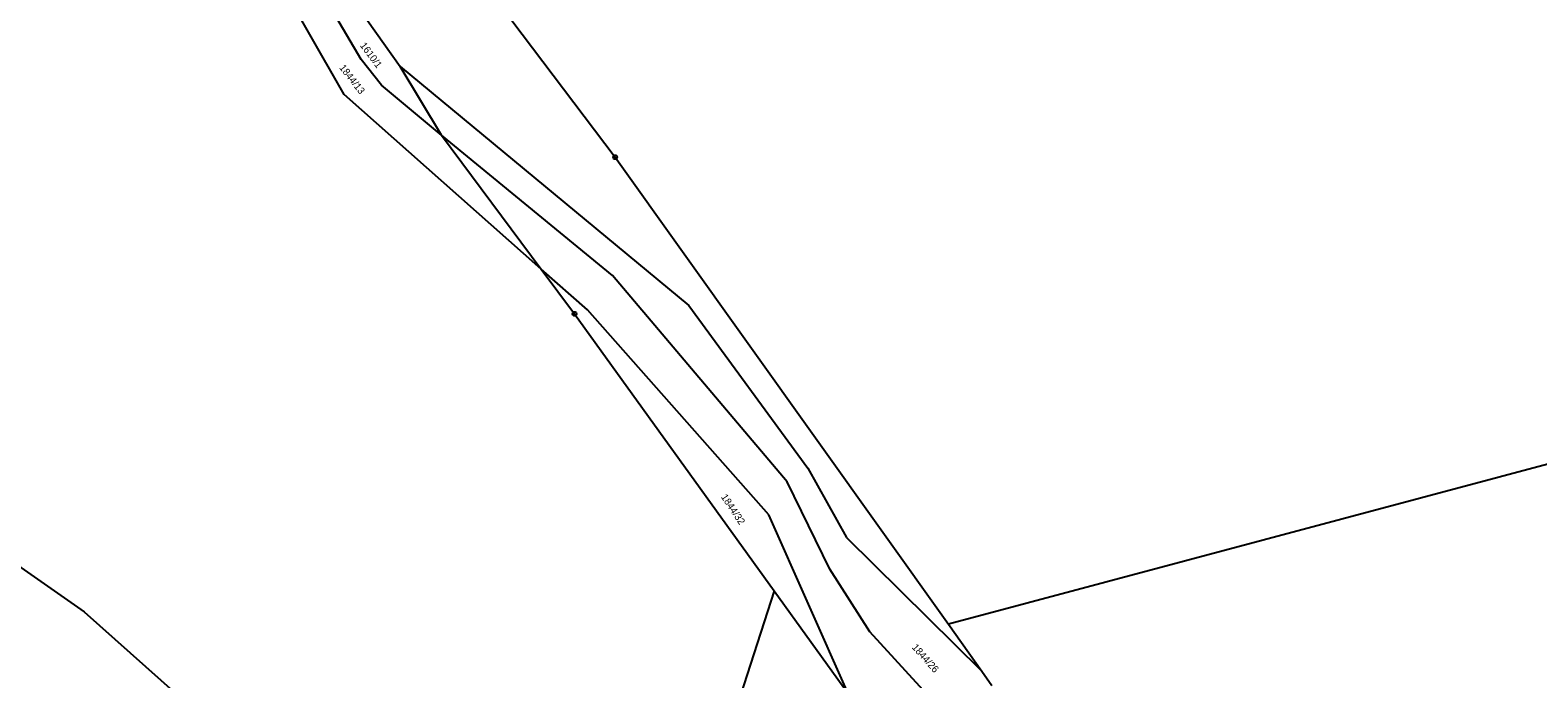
# Model space of a CAD drawing. Extents: x -747792 to -745414, y -1093712 to -1091463.
# Drawn here: x -747209.9 to -747029.6, y -1092023.4 to -1091945.8 of the extents above; entities that cross this region are included whole.
import ezdxf

# ---------------------------------------------------------------- set-up
doc = ezdxf.new("R2010")
doc.units = 0
for name, color, linetype in [('Pracovní_bod JDTM STC_VC', 7, 'Continuous'), ('Pracovní_bod NN - výška', 7, 'Continuous'), ('Pracovní_bod VN - výška', 7, 'Continuous')]:
    doc.layers.add(name, color=color, linetype=linetype)

msp = doc.modelspace()

# ---------------------------------------------------------------- linework, layer by layer
at = {"layer": 'Pracovní_bod NN - výška'}
for points in [[(-747172.39, -1091953.51), (-747197.99, -1091908.69)], [(-747167.26, -1091924.8), (-747139.96, -1091961)], [(-747170.34, -1091949.29), (-747181.15, -1091930.93)], [(-747173.49, -1091939.1), (-747165.68, -1091950.16)], [(-747167.91, -1091952.38), (-747170.34, -1091949.29)], [(-747165.68, -1091950.16), (-747131.13, -1091978.74)], [(-747160.73, -1091958.36), (-747165.68, -1091950.16)], [(-747160.73, -1091958.36), (-747167.91, -1091952.38)], [(-747148.8, -1091974.38), (-747172.39, -1091953.51)], [(-747140.27, -1091975.14), (-747160.73, -1091958.36)], [(-747160.73, -1091958.36), (-747148.8, -1091974.38)], [(-747139.96, -1091961), (-747100.1, -1092016.89)], [(-747143.29, -1091979.25), (-747148.8, -1091974.38)], [(-747148.8, -1091974.38), (-747144.82, -1091979.73)], [(-747119.4, -1091999.85), (-747140.27, -1091975.14)], [(-747121.59, -1092003.79), (-747143.29, -1091979.25)], [(-747131.13, -1091978.74), (-747116.93, -1091998.21)], [(-747144.82, -1091979.73), (-747120.96, -1092012.87)], [(-746977.75, -1091984.22), (-747100.1, -1092016.89)], [(-747116.93, -1091998.21), (-747112.28, -1092006.49)], [(-747114.28, -1092010.31), (-747119.4, -1091999.85)], [(-747112.09, -1092025.19), (-747121.59, -1092003.79)], [(-747112.28, -1092006.49), (-747096.11, -1092022.48)], [(-747214.27, -1092007.85), (-747203.47, -1092015.38)], [(-747109.48, -1092017.78), (-747114.28, -1092010.31)], [(-747120.96, -1092012.87), (-747127.01, -1092031.66)], [(-747120.96, -1092012.87), (-747112.09, -1092025.19)], [(-747203.47, -1092015.38), (-747183.31, -1092033.37)], [(-747100.1, -1092016.89), (-747096.11, -1092022.48)], [(-747090.29, -1092038.83), (-747109.48, -1092017.78)], [(-747096.11, -1092022.48), (-747094.89, -1092024.2)]]:
    msp.add_lwpolyline(points, dxfattribs=at)
at = {"layer": 'Pracovní_bod VN - výška'}
for points in [[(-747139.89, -1091960.76), (-747139.76, -1091960.85), (-747139.71, -1091961), (-747139.76, -1091961.15), (-747139.89, -1091961.24), (-747140.03, -1091961.24), (-747140.16, -1091961.15), (-747140.21, -1091961), (-747140.16, -1091960.85), (-747140.03, -1091960.76)], [(-747144.74, -1091979.49), (-747144.62, -1091979.58), (-747144.57, -1091979.73), (-747144.62, -1091979.88), (-747144.74, -1091979.97), (-747144.9, -1091979.97), (-747145.02, -1091979.88), (-747145.07, -1091979.73), (-747145.02, -1091979.58), (-747144.9, -1091979.49)]]:
    msp.add_lwpolyline(points, close=True, dxfattribs=at)
for points in [[(-747139.98, -1091961), (-747139.93, -1091961)], [(-747144.84, -1091979.73), (-747144.79, -1091979.73)]]:
    msp.add_lwpolyline(points, dxfattribs=at)

# ---------------------------------------------------------------- texts
at = {"layer": 'Pracovní_bod JDTM STC_VC'}
for s, rotation, p in [('1610/1', 306.7043, (-747170.53, -1091947.64)), ('1844/13', 307.8502, (-747173.01, -1091950.3)), ('1844/32', 303.6676, (-747127.34, -1092001.65)), ('1844/26', 311.5172, (-747104.52, -1092019.69))]:
    msp.add_text(s, height=0.85, rotation=rotation, dxfattribs=at).set_placement(p)

doc.saveas('drawing.dxf')
